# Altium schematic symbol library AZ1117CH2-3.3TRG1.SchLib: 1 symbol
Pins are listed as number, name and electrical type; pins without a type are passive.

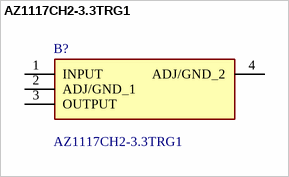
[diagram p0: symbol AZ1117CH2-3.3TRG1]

## AZ1117CH2-3.3TRG1
designator B?
LDO Voltage Regulators LDO BJT HiCurr SOT223 T&R 4K; Manufacturer_Name: Diodes Incorporated; Geometry.Height: 1.8mm
footprint SOT230P700X180-4N
pins: 1 INPUT, 2 ADJ/GND_1, 3 OUTPUT, 4 ADJ/GND_2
